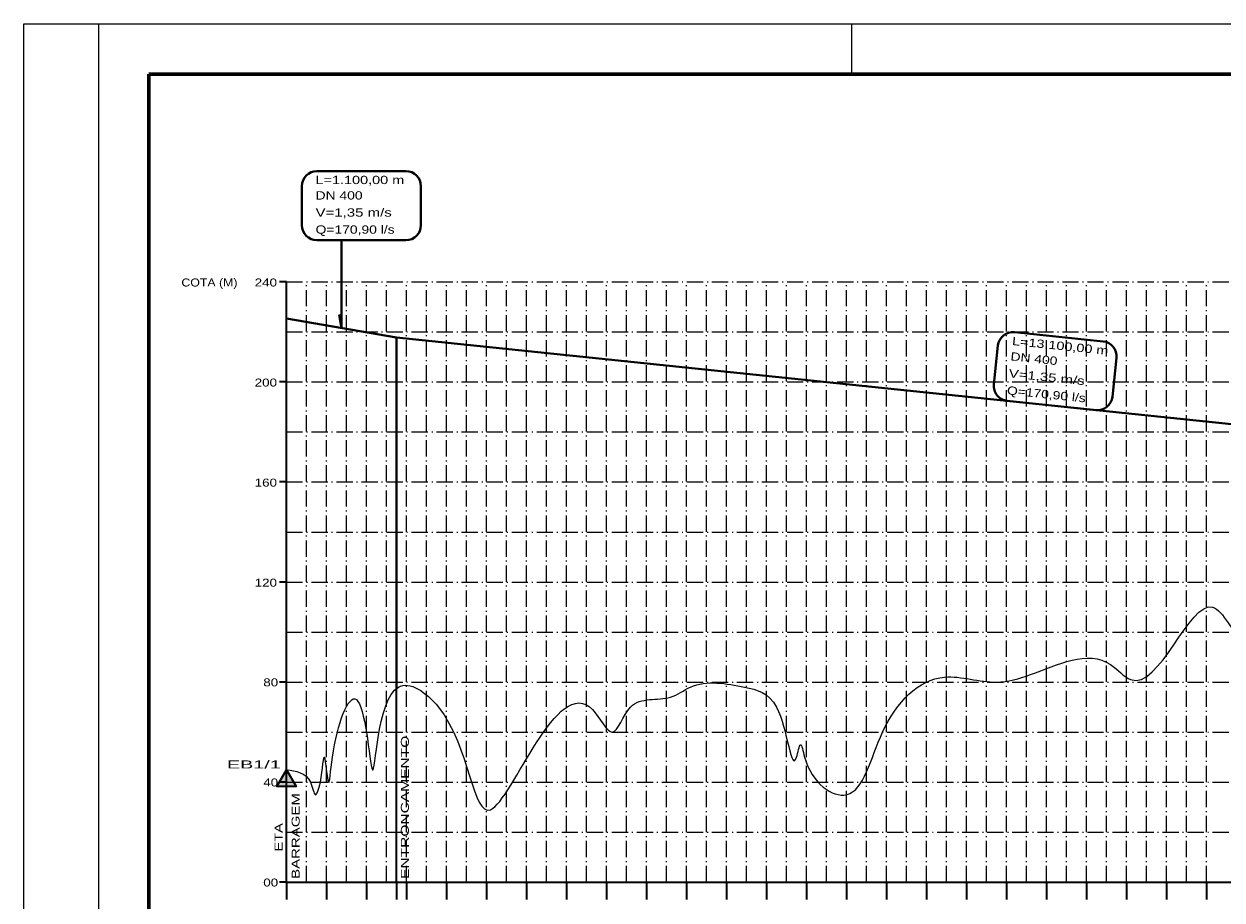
# Model space of a CAD drawing. Extents: x 0 to 1682, y 0 to 1188.
# Drawn here: x -0.2 to 478.9, y 837.7 to 1187.9 of the extents above; entities that cross this region are included whole.
import ezdxf
from ezdxf.enums import TextEntityAlignment as Align

# ---------------------------------------------------------------- set-up
doc = ezdxf.new("R2010")
doc.units = 0
doc.header["$LTSCALE"] = 1.3
doc.linetypes.add('DOT_DASHED', pattern=[7.7, 5, -1.2, 0.3, -1.2])
for name, color, linetype, lineweight in [('1', 7, 'DOT_DASHED', 13), ('55', 7, 'Continuous', 13), ('62', 7, 'Continuous', 13), ('63', 7, 'Continuous', 25), ('9', 7, 'Continuous', 40)]:
    doc.layers.add(name, color=color, linetype=linetype, lineweight=lineweight)
doc.layers.add('24', color=7, linetype='Continuous')

msp = doc.modelspace()

# ---------------------------------------------------------------- hatches: boundary and pattern name
at = {"layer": '62'}
msp.add_hatch(color=256, dxfattribs=at).paths.add_polyline_path([(104.775, 889.796), (108.721, 883.058), (100.912, 883.009)])

# ---------------------------------------------------------------- linework, layer by layer
at = {"layer": '1'}
for p, q in [((104.775, 1084.796), (1296.775, 1084.796)), ((112.775, 844.796), (112.775, 1084.796)), ((120.775, 844.796), (120.775, 1084.796)), ((128.775, 844.796), (128.775, 1084.796)), ((136.775, 844.796), (136.775, 1084.796)), ((144.775, 844.796), (144.775, 1084.796)), ((152.775, 844.796), (152.775, 1084.796)), ((160.775, 844.796), (160.775, 1084.796)), ((168.775, 844.796), (168.775, 1084.796)), ((176.775, 844.796), (176.775, 1084.796)), ((184.775, 844.796), (184.775, 1084.796)), ((192.775, 844.796), (192.775, 1084.796)), ((200.775, 844.796), (200.775, 1084.796)), ((208.775, 844.796), (208.775, 1084.796)), ((216.775, 844.796), (216.775, 1084.796)), ((224.775, 844.796), (224.775, 1084.796)), ((232.775, 844.796), (232.775, 1084.796)), ((240.775, 844.796), (240.775, 1084.796)), ((248.775, 844.796), (248.775, 1084.796)), ((256.775, 844.796), (256.775, 1084.796)), ((264.775, 844.796), (264.775, 1084.796)), ((272.775, 844.796), (272.775, 1084.796)), ((280.775, 844.796), (280.775, 1084.796)), ((288.775, 844.796), (288.775, 1084.796)), ((296.775, 844.796), (296.775, 1084.796)), ((304.775, 844.796), (304.775, 1084.796)), ((312.775, 844.796), (312.775, 1084.796)), ((320.775, 844.796), (320.775, 1084.796)), ((328.775, 844.796), (328.775, 1084.796)), ((336.775, 844.796), (336.775, 1084.796)), ((344.775, 844.796), (344.775, 1084.796)), ((352.775, 844.796), (352.775, 1084.796)), ((360.775, 844.796), (360.775, 1084.796)), ((368.775, 844.796), (368.775, 1084.796)), ((376.775, 844.796), (376.775, 1084.796)), ((384.775, 844.796), (384.775, 1084.796)), ((392.775, 844.796), (392.775, 1084.796)), ((400.775, 844.796), (400.775, 1084.796)), ((408.775, 844.796), (408.775, 1084.796)), ((416.775, 844.796), (416.775, 1084.796)), ((424.775, 844.796), (424.775, 1084.796)), ((432.775, 844.796), (432.775, 1084.796)), ((440.775, 844.796), (440.775, 1084.796)), ((448.775, 844.796), (448.775, 1084.796)), ((456.775, 844.796), (456.775, 1084.796)), ((464.775, 844.796), (464.775, 1084.796)), ((472.775, 844.796), (472.775, 1084.796)), ((104.775, 1064.796), (1296.775, 1064.796)), ((104.775, 1044.796), (1296.775, 1044.796)), ((104.775, 1024.796), (1296.775, 1024.796)), ((104.775, 1004.796), (1296.775, 1004.796)), ((104.775, 984.796), (1296.775, 984.796)), ((104.775, 964.796), (1296.775, 964.796)), ((104.775, 944.796), (1296.775, 944.796)), ((112.775, 844.796), (112.775, 930.847)), ((120.775, 844.796), (120.775, 930.847)), ((128.775, 844.796), (128.775, 930.847)), ((136.775, 844.796), (136.775, 930.847)), ((144.775, 844.796), (144.775, 930.847)), ((152.775, 844.796), (152.775, 930.847)), ((104.775, 924.796), (157.211, 924.796)), ((104.775, 924.796), (1296.775, 924.796)), ((104.775, 904.796), (157.211, 904.796)), ((104.775, 904.796), (1296.775, 904.796)), ((104.775, 884.796), (157.211, 884.796)), ((104.775, 884.796), (1296.775, 884.796)), ((104.775, 864.796), (157.211, 864.796)), ((104.775, 864.796), (1296.775, 864.796))]:
    msp.add_line(p, q, dxfattribs=at)
at = {"layer": '55'}
msp.add_spline([(104.775, 889.796), (114.375, 884.796), (116.375, 879.796), (118.375, 884.796), (119.975, 894.796), (121.575, 884.796), (123.175, 894.796), (132.775, 917.796), (136.775, 904.796), (139.175, 889.796), (149.575, 922.796), (165.575, 914.796), (186.375, 873.796), (227.175, 913.796), (235.175, 904.796), (242.375, 914.796), (258.375, 918.796), (266.375, 922.796), (287.975, 922.796), (300.775, 914.796), (308.775, 894.796), (310.375, 899.796), (311.975, 894.796), (328.775, 879.796), (343.175, 904.796), (367.975, 926.796), (388.775, 924.796), (402.375, 927.796), (434.375, 931.796), (442.375, 925.796), (475.175, 954.796), (488.775, 939.796), (492.775, 937.796), (524.775, 949.796), (534.375, 944.796), (536.775, 941.796), (551.175, 956.796), (559.175, 958.796), (579.175, 944.796), (588.775, 954.796), (595.175, 944.796), (607.175, 934.796), (615.975, 947.796), (631.975, 929.796), (651.975, 894.796), (653.575, 889.796), (659.975, 909.796), (663.175, 904.796), (669.575, 898.796), (687.975, 886.796), (697.575, 888.796), (703.975, 886.796), (707.975, 894.796), (711.975, 890.796), (728.775, 894.796), (731.975, 896.796), (734.375, 894.796), (753.575, 910.796), (767.975, 889.796), (787.975, 914.796), (806.375, 922.796), (826.375, 898.796), (830.375, 904.796), (837.575, 897.796), (841.575, 899.796), (846.375, 904.796), (850.375, 889.796), (854.375, 902.796), (863.975, 899.796), (878.375, 924.796), (911.175, 941.796), (923.975, 927.796), (936.775, 937.796), (955.175, 931.796), (969.575, 939.796), (1002.375, 919.796), (1022.375, 939.796), (1070.375, 954.796), (1088.775, 937.796), (1096.775, 944.796), (1103.975, 938.796), (1124.775, 959.796), (1148.775, 940.796), (1153.575, 944.796), (1156.775, 937.796), (1166.644, 960.143), (1170.611, 963.809), (1176.775, 959.796)], degree=3, dxfattribs=at)
at = {"layer": '62', "lineweight": 35}
for p, q in [((104.775, 1084.796), (102.044, 1084.796)), ((104.607, 1084.796), (104.775, 1084.796)), ((104.775, 844.796), (104.775, 1084.796)), ((104.607, 1074.796), (104.775, 1074.796)), ((104.607, 1064.796), (104.775, 1064.796)), ((104.607, 1054.796), (104.775, 1054.796)), ((104.775, 1044.796), (102.044, 1044.796)), ((104.607, 1044.796), (104.775, 1044.796)), ((104.607, 1034.796), (104.775, 1034.796)), ((104.607, 1024.796), (104.775, 1024.796)), ((104.607, 1014.796), (104.775, 1014.796)), ((104.775, 1004.796), (102.044, 1004.796)), ((104.607, 1004.796), (104.775, 1004.796)), ((104.607, 994.796), (104.775, 994.796)), ((104.607, 984.796), (104.775, 984.796)), ((104.607, 974.796), (104.775, 974.796)), ((104.775, 964.796), (102.044, 964.796)), ((104.607, 964.796), (104.775, 964.796)), ((104.607, 954.796), (104.775, 954.796)), ((104.607, 944.796), (104.775, 944.796)), ((104.607, 934.796), (104.775, 934.796)), ((104.775, 844.796), (104.775, 930.847)), ((104.775, 924.796), (102.044, 924.796)), ((104.775, 924.796), (102.044, 924.796)), ((104.607, 924.796), (104.775, 924.796)), ((104.607, 924.796), (104.775, 924.796)), ((148.775, 844.796), (148.775, 922.747)), ((104.607, 914.796), (104.775, 914.796)), ((104.607, 914.796), (104.775, 914.796)), ((104.607, 904.796), (104.775, 904.796)), ((104.607, 904.796), (104.775, 904.796)), ((104.607, 894.796), (104.775, 894.796)), ((104.607, 894.796), (104.775, 894.796)), ((104.775, 884.796), (102.044, 884.796)), ((104.607, 884.796), (104.775, 884.796)), ((104.607, 884.796), (104.775, 884.796)), ((104.607, 874.796), (104.775, 874.796)), ((104.607, 874.796), (104.775, 874.796)), ((104.607, 864.796), (104.775, 864.796)), ((104.607, 864.796), (104.775, 864.796)), ((104.607, 854.796), (104.775, 854.796)), ((104.607, 854.796), (104.775, 854.796)), ((104.775, 844.796), (102.044, 844.796)), ((104.775, 844.796), (102.044, 844.796)), ((104.775, 844.796), (104.775, 837.968)), ((104.775, 844.796), (104.775, 837.968)), ((104.775, 844.796), (157.211, 844.796)), ((120.775, 844.796), (120.775, 837.968)), ((120.775, 844.796), (120.775, 837.968)), ((136.775, 844.796), (136.775, 837.968)), ((136.775, 844.796), (136.775, 837.968)), ((148.775, 844.796), (148.775, 837.968)), ((148.775, 844.796), (148.775, 837.968)), ((152.775, 844.796), (152.775, 837.968)), ((152.775, 844.796), (152.775, 837.968)), ((168.775, 844.796), (168.775, 837.968)), ((184.775, 844.796), (184.775, 837.968)), ((200.775, 844.796), (200.775, 837.968)), ((216.775, 844.796), (216.775, 837.968)), ((232.775, 844.796), (232.775, 837.968)), ((248.775, 844.796), (248.775, 837.968)), ((264.775, 844.796), (264.775, 837.968)), ((280.775, 844.796), (280.775, 837.968)), ((296.775, 844.796), (296.775, 837.968)), ((312.775, 844.796), (312.775, 837.968)), ((328.775, 844.796), (328.775, 837.968)), ((344.775, 844.796), (344.775, 837.968)), ((360.775, 844.796), (360.775, 837.968)), ((376.775, 844.796), (376.775, 837.968)), ((392.775, 844.796), (392.775, 837.968)), ((408.775, 844.796), (408.775, 837.968)), ((424.775, 844.796), (424.775, 837.968)), ((440.775, 844.796), (440.775, 837.968)), ((456.775, 844.796), (456.775, 837.968)), ((472.775, 844.796), (472.775, 837.968))]:
    msp.add_line(p, q, dxfattribs=at)
at = {"layer": '62'}
for p, q in [((104.607, 1082.796), (104.775, 1082.796)), ((104.607, 1080.796), (104.775, 1080.796)), ((104.607, 1078.796), (104.775, 1078.796)), ((104.607, 1076.796), (104.775, 1076.796)), ((104.607, 1072.796), (104.775, 1072.796)), ((104.607, 1070.796), (104.775, 1070.796)), ((104.607, 1068.796), (104.775, 1068.796)), ((104.607, 1066.796), (104.775, 1066.796)), ((104.607, 1062.796), (104.775, 1062.796)), ((104.607, 1060.796), (104.775, 1060.796)), ((104.607, 1058.796), (104.775, 1058.796)), ((104.607, 1056.796), (104.775, 1056.796)), ((104.607, 1052.796), (104.775, 1052.796)), ((104.607, 1050.796), (104.775, 1050.796)), ((104.607, 1048.796), (104.775, 1048.796)), ((104.607, 1046.796), (104.775, 1046.796)), ((104.607, 1042.796), (104.775, 1042.796)), ((104.607, 1040.796), (104.775, 1040.796)), ((104.607, 1038.796), (104.775, 1038.796)), ((104.607, 1036.796), (104.775, 1036.796)), ((104.607, 1032.796), (104.775, 1032.796)), ((104.607, 1030.796), (104.775, 1030.796)), ((104.607, 1028.796), (104.775, 1028.796)), ((104.607, 1026.796), (104.775, 1026.796)), ((104.607, 1022.796), (104.775, 1022.796)), ((104.607, 1020.796), (104.775, 1020.796)), ((104.607, 1018.796), (104.775, 1018.796)), ((104.607, 1016.796), (104.775, 1016.796)), ((104.607, 1012.796), (104.775, 1012.796)), ((104.607, 1010.796), (104.775, 1010.796)), ((104.607, 1008.796), (104.775, 1008.796)), ((104.607, 1006.796), (104.775, 1006.796)), ((104.607, 1002.796), (104.775, 1002.796)), ((104.607, 1000.796), (104.775, 1000.796)), ((104.607, 998.796), (104.775, 998.796)), ((104.607, 996.796), (104.775, 996.796)), ((104.607, 992.796), (104.775, 992.796)), ((104.607, 990.796), (104.775, 990.796)), ((104.607, 988.796), (104.775, 988.796)), ((104.607, 986.796), (104.775, 986.796)), ((104.607, 982.796), (104.775, 982.796)), ((104.607, 980.796), (104.775, 980.796)), ((104.607, 978.796), (104.775, 978.796)), ((104.607, 976.796), (104.775, 976.796)), ((104.607, 972.796), (104.775, 972.796)), ((104.607, 970.796), (104.775, 970.796)), ((104.607, 968.796), (104.775, 968.796)), ((104.607, 966.796), (104.775, 966.796)), ((104.607, 962.796), (104.775, 962.796)), ((104.607, 960.796), (104.775, 960.796)), ((104.607, 958.796), (104.775, 958.796)), ((104.607, 956.796), (104.775, 956.796)), ((104.607, 952.796), (104.775, 952.796)), ((104.607, 950.796), (104.775, 950.796)), ((104.607, 948.796), (104.775, 948.796)), ((104.607, 946.796), (104.775, 946.796)), ((104.607, 942.796), (104.775, 942.796)), ((104.607, 940.796), (104.775, 940.796)), ((104.607, 938.796), (104.775, 938.796)), ((104.607, 936.796), (104.775, 936.796)), ((104.607, 932.796), (104.775, 932.796)), ((104.607, 930.796), (104.775, 930.796)), ((104.607, 930.796), (104.775, 930.796)), ((104.607, 928.796), (104.775, 928.796)), ((104.607, 928.796), (104.775, 928.796)), ((104.607, 926.796), (104.775, 926.796)), ((104.607, 926.796), (104.775, 926.796)), ((104.607, 922.796), (104.775, 922.796)), ((104.607, 922.796), (104.775, 922.796)), ((104.607, 920.796), (104.775, 920.796)), ((104.607, 920.796), (104.775, 920.796)), ((104.607, 918.796), (104.775, 918.796)), ((104.607, 918.796), (104.775, 918.796)), ((104.607, 916.796), (104.775, 916.796)), ((104.607, 916.796), (104.775, 916.796)), ((104.607, 912.796), (104.775, 912.796)), ((104.607, 912.796), (104.775, 912.796)), ((104.607, 910.796), (104.775, 910.796)), ((104.607, 910.796), (104.775, 910.796)), ((104.607, 908.796), (104.775, 908.796)), ((104.607, 908.796), (104.775, 908.796)), ((104.607, 906.796), (104.775, 906.796)), ((104.607, 906.796), (104.775, 906.796)), ((104.607, 902.796), (104.775, 902.796)), ((104.607, 902.796), (104.775, 902.796)), ((104.607, 900.796), (104.775, 900.796)), ((104.607, 900.796), (104.775, 900.796)), ((104.607, 898.796), (104.775, 898.796)), ((104.607, 898.796), (104.775, 898.796)), ((104.607, 896.796), (104.775, 896.796)), ((104.607, 896.796), (104.775, 896.796)), ((104.607, 892.796), (104.775, 892.796)), ((104.607, 892.796), (104.775, 892.796)), ((104.607, 890.796), (104.775, 890.796)), ((104.607, 890.796), (104.775, 890.796)), ((104.607, 888.796), (104.775, 888.796)), ((104.607, 888.796), (104.775, 888.796)), ((104.607, 886.796), (104.775, 886.796)), ((104.607, 886.796), (104.775, 886.796)), ((104.607, 882.796), (104.775, 882.796)), ((104.607, 882.796), (104.775, 882.796)), ((104.607, 880.796), (104.775, 880.796)), ((104.607, 880.796), (104.775, 880.796)), ((104.607, 878.796), (104.775, 878.796)), ((104.607, 878.796), (104.775, 878.796)), ((104.607, 876.796), (104.775, 876.796)), ((104.607, 876.796), (104.775, 876.796)), ((104.607, 872.796), (104.775, 872.796)), ((104.607, 872.796), (104.775, 872.796)), ((104.607, 870.796), (104.775, 870.796)), ((104.607, 870.796), (104.775, 870.796)), ((104.607, 868.796), (104.775, 868.796)), ((104.607, 868.796), (104.775, 868.796)), ((104.607, 866.796), (104.775, 866.796)), ((104.607, 866.796), (104.775, 866.796)), ((104.607, 862.796), (104.775, 862.796)), ((104.607, 862.796), (104.775, 862.796)), ((104.607, 860.796), (104.775, 860.796)), ((104.607, 860.796), (104.775, 860.796)), ((104.607, 858.796), (104.775, 858.796)), ((104.607, 858.796), (104.775, 858.796)), ((104.607, 856.796), (104.775, 856.796)), ((104.607, 856.796), (104.775, 856.796)), ((104.607, 852.796), (104.775, 852.796)), ((104.607, 852.796), (104.775, 852.796)), ((104.607, 850.796), (104.775, 850.796)), ((104.607, 850.796), (104.775, 850.796)), ((104.607, 848.796), (104.775, 848.796)), ((104.607, 848.796), (104.775, 848.796)), ((104.607, 846.796), (104.775, 846.796)), ((104.607, 846.796), (104.775, 846.796))]:
    msp.add_line(p, q, dxfattribs=at)
at = {"layer": '62', "lineweight": 35}
msp.add_lwpolyline([(104.775, 889.796), (108.721, 883.058), (100.912, 883.009)], close=True, dxfattribs=at)
for points in [[(104.607, 884.796), (104.775, 884.796), (102.044, 884.796)], [(104.775, 844.796), (384.775, 844.796), (1176.775, 844.796)]]:
    msp.add_lwpolyline(points, dxfattribs=at)
at = {"layer": '63'}
for p, q in [((-0.168, 1187.881), (1681.832, 1187.881)), ((-0.168, -0.119), (-0.168, 1187.881)), ((29.832, 593.881), (29.832, 1187.881)), ((330.832, 1167.881), (330.832, 1187.881))]:
    msp.add_line(p, q, dxfattribs=at)
at = {"layer": '63', "lineweight": 60}
for points in [[(49.832, 1167.881), (1661.832, 1167.881), (1661.832, 19.881), (1311.832, 19.881)], [(951.544, 19.881), (49.832, 19.881), (49.832, 1167.881)]]:
    msp.add_lwpolyline(points, dxfattribs=at)
at = {"layer": '9'}
for p, q in [((116.958, 1129.052), (152.592, 1129.052)), ((110.958, 1123.052), (110.958, 1107.441)), ((158.592, 1123.052), (158.592, 1107.441)), ((116.958, 1101.441), (152.592, 1101.441)), ((395.899, 1064.676), (431.343, 1061.003)), ((148.775, 922.796), (148.775, 1062.526)), ((389.312, 1059.326), (387.703, 1043.799)), ((436.692, 1054.416), (435.083, 1038.889)), ((393.053, 1037.212), (428.497, 1033.539))]:
    msp.add_line(p, q, dxfattribs=at)
for points in [[(125.943, 1071.741), (126.775, 1066.306), (126.775, 1101.441)], [(104.775, 1070.086), (148.775, 1062.526), (672.775, 1008.226), (1176.775, 964.796)]]:
    msp.add_lwpolyline(points, dxfattribs=at)
for centre, start, end in [((116.958, 1123.052), 90, 180), ((152.592, 1123.052), 0, 90), ((116.958, 1107.441), 180, 270), ((152.592, 1107.441), 270, 0), ((395.28, 1058.708), 84.08379, 174.08379), ((430.724, 1055.035), 354.08379, 84.08379), ((393.671, 1043.18), 174.08379, 264.08379), ((429.115, 1039.507), 264.08379, 354.08379)]:
    msp.add_arc(centre, 6, start, end, dxfattribs=at)

# ---------------------------------------------------------------- texts
at = {"layer": '24'}
for s, width, p in [('COTA (M)', 1.15, (85.214, 1082.94)), ('240', 1.25, (101.021, 1082.94)), ('200', 1.25, (101.021, 1042.94)), ('160', 1.25, (101.021, 1002.94)), ('120', 1.25, (101.021, 962.94)), ('80', 1.25, (101.486, 923.095)), ('40', 1.25, (101.486, 883.095)), ('00', 1.25, (101.486, 843.095))]:
    msp.add_text(s, height=3.2, dxfattribs=dict(at, width=width)).set_placement(p, align=Align.RIGHT)
for s, width, p in [('ENTRONCAMENTO', 1.45, (153.759, 846.141)), ('BARRAGEM', 1.4, (110.079, 846.141)), ('ETA', 1.35, (103.228, 857.144))]:
    msp.add_text(s, height=3.2, rotation=90, dxfattribs=dict(at, width=width)).set_placement(p)
at = {"layer": '24', "width": 1.85}
msp.add_text('EB1/1', height=3.2, dxfattribs=at).set_placement((80.988, 890.291))
at = {"layer": '9'}
for s, width, p in [('L=1.100,00 m', 1.3, (116.443, 1123.873)), ('DN 400', 1.25, (116.443, 1117.693)), ('V=1,35 m/s', 1.35, (116.443, 1110.87)), ('Q=170,90 l/s', 1.25, (116.443, 1104.046))]:
    msp.add_text(s, height=3.319, dxfattribs=dict(at, width=width)).set_placement(p)
for s, width, p in [('L=13.100,00 m', 1.3, (394.852, 1059.578)), ('DN 400', 1.25, (394.215, 1053.431)), ('V=1,35 m/s', 1.35, (393.512, 1046.644)), ('Q=170,90 l/s', 1.25, (392.809, 1039.856))]:
    msp.add_text(s, height=3.319, rotation=354.084, dxfattribs=dict(at, width=width)).set_placement(p)

doc.saveas('drawing.dxf')
